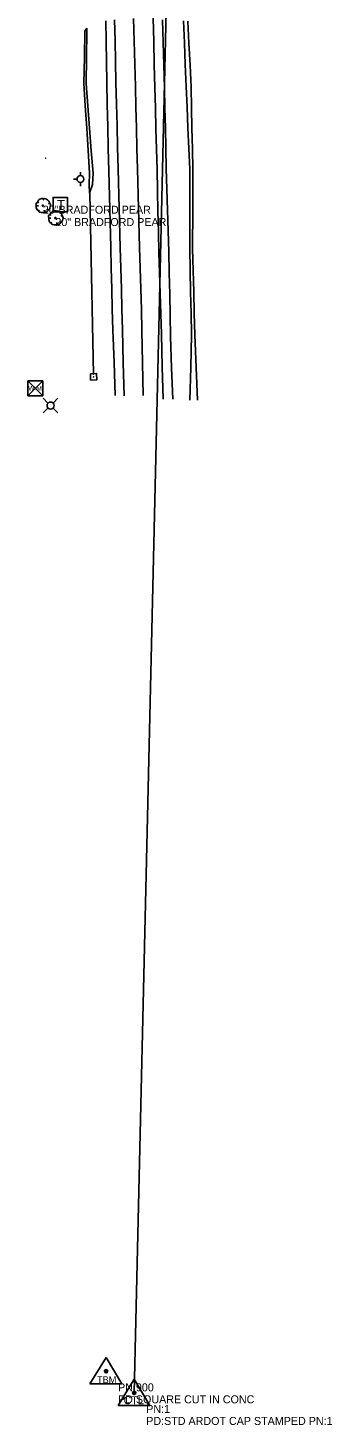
# Model space of a CAD drawing. Extents: x 1930288 to 1941089, y 588389 to 611475.
# Drawn here: x 1930835 to 1931025, y 596253 to 597126 of the extents above; entities that cross this region are included whole.
import ezdxf

# ---------------------------------------------------------------- set-up
doc = ezdxf.new("R2010")
doc.units = 0
for name, color, linetype in [('S_BASELINE', 7, 'Continuous'), ('S_DITCHLINE', 7, 'Continuous'), ('S_DRG_PT_SYM', 7, 'Continuous'), ('S_DROP_INLET', 7, 'Continuous'), ('S_EDGE_PAVEMENT', 7, 'Continuous'), ('S_MSC_PT_SYM', 7, 'Continuous'), ('S_PAVEMENT_CROWN', 7, 'Continuous'), ('S_PRIMARY_CTL', 7, 'Continuous'), ('S_PRIMARY_CTL_ANNOT', 7, 'Continuous'), ('S_SHOULDER', 7, 'Continuous'), ('S_STORM_SEWER', 7, 'Continuous'), ('S_TELEPHONE_UTILITIES', 7, 'Continuous'), ('S_TREE', 7, 'Continuous'), ('S_TREE_ANNOT', 7, 'Continuous'), ('S_UTILITY_POLE', 7, 'Continuous'), ('S_UTL_PT_SYM', 7, 'Continuous'), ('S_WATER_UTILITIES', 7, 'Continuous')]:
    doc.layers.add(name, color=color, linetype=linetype)

msp = doc.modelspace()

# ---------------------------------------------------------------- linework, layer by layer
at = {"layer": 'S_BASELINE'}
msp.add_line((1930901.19, 596273.28), (1930922.05, 597172.86), dxfattribs=at)
at = {"layer": 'S_DITCHLINE'}
for points in [[(1930935.96, 596893.42), (1930936.43, 596913.86), (1930936.9, 596934.29), (1930936.64, 596947.76), (1930936.39, 596961.23), (1930936.13, 596974.71), (1930935.87, 596988.18), (1930935.84, 597012.94), (1930935.8, 597037.7), (1930935.27, 597050.64), (1930934.74, 597063.57), (1930934.21, 597076.51), (1930933.67, 597089.44), (1930933.09, 597103.12), (1930932.51, 597116.8), (1930931.93, 597130.48)], [(1930940.76, 596893.51), (1930939.91, 596913.94), (1930939.07, 596934.38), (1930938.71, 596947.77), (1930938.36, 596961.16), (1930938.01, 596974.55), (1930937.65, 596987.94), (1930937.7, 597012.78), (1930937.75, 597037.63), (1930937.5, 597050.49), (1930937.24, 597063.34), (1930936.99, 597076.2), (1930936.73, 597089.05), (1930936.05, 597102.82), (1930935.37, 597116.58), (1930934.68, 597130.34)], [(1930871.61, 597125.83), (1930870.43, 597123.96), (1930870.11, 597107.71), (1930869.78, 597091.46), (1930870.65, 597077.43), (1930871.52, 597063.41), (1930872.39, 597049.39), (1930873.26, 597035.36), (1930873.14, 597028.29), (1930873.33, 597022.72)], [(1930871.61, 597125.83), (1930871.61, 597123.69), (1930871.36, 597107.55), (1930871.12, 597091.41), (1930872.21, 597077.38), (1930873.3, 597063.34), (1930874.39, 597049.31), (1930875.49, 597035.28), (1930875.21, 597028.14), (1930873.33, 597022.73)]]:
    msp.add_lwpolyline(points, dxfattribs=at)
at = {"layer": 'S_DRG_PT_SYM'}
msp.add_lwpolyline([(1930875.81, 596908.03), (1930875.81, 596908.08), (1930875.81, 596908.03), (1930875.76, 596908.03), (1930875.81, 596908.03), (1930875.81, 596907.98), (1930875.81, 596908.03), (1930875.86, 596908.03)], dxfattribs=at)
at = {"layer": 'S_DROP_INLET'}
msp.add_lwpolyline([(1930873.91, 596909.94), (1930877.76, 596910.21), (1930877.89, 596906.21), (1930873.97, 596906.02)], close=True, dxfattribs=at)
at = {"layer": 'S_EDGE_PAVEMENT'}
for points in [[(1930888.95, 597131.01), (1930889.24, 597118), (1930889.53, 597104.99), (1930889.82, 597091.97), (1930890.15, 597078.5), (1930890.49, 597065.03), (1930890.83, 597051.56), (1930891.16, 597038.09), (1930891.82, 597013.43), (1930892.48, 596988.78), (1930892.83, 596975.95), (1930893.19, 596963.12), (1930893.54, 596950.29), (1930893.89, 596937.46), (1930894.39, 596916.81), (1930894.9, 596896.15)], [(1930912.96, 597132.04), (1930913.35, 597117.63), (1930913.73, 597103.21), (1930914.11, 597088.8), (1930914.45, 597075.97), (1930914.78, 597063.15), (1930915.11, 597050.33), (1930915.44, 597037.5), (1930915.72, 597024.56), (1930916.01, 597011.62), (1930916.29, 596998.68), (1930916.58, 596985.74), (1930916.97, 596972.98), (1930917.37, 596960.21), (1930917.76, 596947.44), (1930918.15, 596934.67), (1930918.7, 596914.36), (1930919.25, 596894.06)]]:
    msp.add_lwpolyline(points, dxfattribs=at)
at = {"layer": 'S_MSC_PT_SYM'}
for points in [[(1930845.93, 597044.71), (1930845.93, 597044.76), (1930845.93, 597044.71), (1930845.88, 597044.71), (1930845.93, 597044.71), (1930845.93, 597044.66), (1930845.93, 597044.71), (1930845.98, 597044.71)], [(1930852.43, 597006.83), (1930852.43, 597006.88), (1930852.43, 597006.83), (1930852.38, 597006.83), (1930852.43, 597006.83), (1930852.43, 597006.78), (1930852.43, 597006.83), (1930852.48, 597006.83)]]:
    msp.add_lwpolyline(points, dxfattribs=at)
at = {"layer": 'S_PAVEMENT_CROWN'}
msp.add_lwpolyline([(1930900.73, 597131.95), (1930901.14, 597117.75), (1930901.56, 597103.54), (1930901.97, 597089.34), (1930902.27, 597076.48), (1930902.58, 597063.63), (1930902.88, 597050.77), (1930903.18, 597037.91), (1930903.84, 597013.39), (1930904.5, 596988.86), (1930904.88, 596975.92), (1930905.27, 596962.98), (1930905.65, 596950.04), (1930906.03, 596937.1), (1930906.41, 596916.76), (1930906.79, 596896.43)], dxfattribs=at)
at = {"layer": 'S_PRIMARY_CTL'}
for p, q in [((1930883.6, 596295.48), (1930873.57, 596278.96)), ((1930883.6, 596295.48), (1930893.42, 596278.96)), ((1930873.57, 596278.96), (1930893.42, 596278.96)), ((1930901.19, 596281.98), (1930891.16, 596265.47)), ((1930901.19, 596281.98), (1930911.01, 596265.47)), ((1930891.16, 596265.47), (1930911.01, 596265.47))]:
    msp.add_line(p, q, dxfattribs=at)
for centre, radius in [((1930883.6, 596286.78), 1.04), ((1930883.6, 596286.78), 0.609), ((1930883.6, 596286.78), 0.344), ((1930901.19, 596273.28), 1.04), ((1930901.19, 596273.28), 0.609), ((1930901.19, 596273.28), 0.344)]:
    msp.add_circle(centre, radius, dxfattribs=at)
at = {"layer": 'S_SHOULDER'}
for points in [[(1930883.43, 597130.36), (1930883.65, 597117.6), (1930883.87, 597104.84), (1930884.1, 597092.08), (1930884.4, 597078.25), (1930884.7, 597064.43), (1930885.01, 597050.61), (1930885.31, 597036.79), (1930885.95, 597012.83), (1930886.59, 596988.87), (1930886.91, 596975.99), (1930887.22, 596963.11), (1930887.53, 596950.23), (1930887.85, 596937.36), (1930888.6, 596916.91), (1930889.35, 596896.46)], [(1930918.82, 597130.98), (1930919.27, 597116.87), (1930919.71, 597102.76), (1930920.15, 597088.65), (1930920.4, 597076.06), (1930920.65, 597063.46), (1930920.9, 597050.86), (1930921.16, 597038.27), (1930921.57, 597025.24), (1930921.98, 597012.22), (1930922.39, 596999.2), (1930922.8, 596986.17), (1930923.06, 596972.95), (1930923.33, 596959.72), (1930923.59, 596946.5), (1930923.85, 596933.27), (1930924.52, 596913.69), (1930925.2, 596894.1)]]:
    msp.add_lwpolyline(points, dxfattribs=at)
at = {"layer": 'S_STORM_SEWER'}
msp.add_line((1930875.71, 596909.68), (1930873.41, 597022.7), dxfattribs=at)
at = {"layer": 'S_TELEPHONE_UTILITIES'}
msp.add_lwpolyline([(1930850.51, 597011.12), (1930850.51, 597020.12), (1930859.51, 597020.12), (1930859.51, 597011.12)], close=True, dxfattribs=at)
at = {"layer": 'S_TREE'}
for p, q in [((1930840.94, 597017.2), (1930841.44, 597016.62)), ((1930844.73, 597019.21), (1930844.35, 597018.36)), ((1930840.28, 597014.87), (1930841.4, 597014.87)), ((1930841.44, 597011.69), (1930841.9, 597012.39)), ((1930845.12, 597011.42), (1930845.04, 597012.2)), ((1930847.52, 597012.31), (1930847.06, 597012.74)), ((1930848.3, 597016.42), (1930847.64, 597016.15)), ((1930848.75, 597009.49), (1930849.26, 597008.91)), ((1930852.55, 597011.51), (1930852.16, 597010.65)), ((1930856.12, 597008.72), (1930855.46, 597008.45)), ((1930848.1, 597007.17), (1930849.22, 597007.17)), ((1930849.26, 597003.99), (1930849.72, 597004.69)), ((1930852.94, 597003.72), (1930852.86, 597004.49)), ((1930855.34, 597004.61), (1930854.88, 597005.04))]:
    msp.add_line(p, q, dxfattribs=at)
for centre in [(1930844.18, 597014.97), (1930851.99, 597007.26)]:
    msp.add_circle(centre, 0.341, dxfattribs=at)
for centre, major_axis, ratio, start_param, end_param in [((1930840.6, 597016.05), (0.31, 1.03), 0.646762, 0, 3.141593), ((1930842.84, 597018.17), (1.86, 1.08), 0.471018, 0, 3.141593), ((1930846.49, 597017.84), (-1.81, 1.36), 0.405113, 3.141593, 6.283186), ((1930840.91, 597013.4), (-0.61, 1.6), 0.420543, 6.283185, 9.424777), ((1930843.37, 597011.62), (-1.83, 0.19), 0.529943, 0, 3.141593), ((1930846.33, 597011.92), (1.09, 0.46), 0.711534, 3.141592, 6.283185), ((1930847.85, 597014.44), (0.46, 2.04), 0.482994, 3.141593, 6.283185), ((1930848.42, 597008.35), (0.31, 1.03), 0.646762, 0, 3.141593), ((1930850.66, 597010.46), (1.86, 1.08), 0.471018, 0, 3.141593), ((1930854.31, 597010.14), (-1.81, 1.36), 0.405113, 3.141593, 6.283186), ((1930855.67, 597006.73), (0.46, 2.04), 0.482994, 3.141593, 6.283185), ((1930848.73, 597005.7), (-0.61, 1.6), 0.420543, 6.283185, 9.424777), ((1930851.19, 597003.92), (-1.83, 0.19), 0.529943, 0, 3.141593), ((1930854.15, 597004.21), (1.09, 0.46), 0.711534, 3.141592, 6.283185)]:
    msp.add_ellipse(centre, major_axis=major_axis, ratio=ratio, start_param=start_param, end_param=end_param, dxfattribs=at)
at = {"layer": 'S_UTILITY_POLE'}
for p, q in [((1930867.63, 597033.74), (1930867.63, 597035.99)), ((1930865.54, 597031.61), (1930863.22, 597031.61)), ((1930867.71, 597027.19), (1930867.71, 597029.52)), ((1930847.38, 596891.68), (1930844.4, 596894.66)), ((1930850.56, 596891.68), (1930853.55, 596894.66)), ((1930847.38, 596888.5), (1930844.4, 596885.52)), ((1930850.56, 596888.5), (1930853.55, 596885.52))]:
    msp.add_line(p, q, dxfattribs=at)
for centre, radius in [((1930867.64, 597031.63), 2.13), ((1930848.98, 596890.1), 2.21)]:
    msp.add_circle(centre, radius, dxfattribs=at)
at = {"layer": 'S_UTL_PT_SYM'}
for points in [[(1930873.41, 597022.7), (1930873.41, 597022.75), (1930873.41, 597022.7), (1930873.36, 597022.7), (1930873.41, 597022.7), (1930873.41, 597022.65), (1930873.41, 597022.7), (1930873.46, 597022.7)], [(1930875.71, 596909.68), (1930875.71, 596909.73), (1930875.71, 596909.68), (1930875.66, 596909.68), (1930875.71, 596909.68), (1930875.71, 596909.63), (1930875.71, 596909.68), (1930875.76, 596909.68)], [(1930875.81, 596908.03), (1930875.81, 596908.08), (1930875.81, 596908.03), (1930875.76, 596908.03), (1930875.81, 596908.03), (1930875.81, 596907.98), (1930875.81, 596908.03), (1930875.86, 596908.03)]]:
    msp.add_lwpolyline(points, dxfattribs=at)
at = {"layer": 'S_WATER_UTILITIES'}
for p, q in [((1930834.89, 596905.65), (1930844.23, 596905.65)), ((1930834.89, 596905.65), (1930834.89, 596896.16)), ((1930834.89, 596905.65), (1930844.23, 596896.16)), ((1930844.23, 596905.65), (1930834.89, 596896.16)), ((1930844.23, 596905.65), (1930844.23, 596896.16)), ((1930834.89, 596896.16), (1930844.23, 596896.16))]:
    msp.add_line(p, q, dxfattribs=at)

# ---------------------------------------------------------------- texts
at = {"layer": 'S_PRIMARY_CTL'}
for s, height, p in [('TBM', 4.287, (1930877.95, 596279.39)), ('CTL', 5, (1930894.6, 596266.21))]:
    msp.add_text(s, height=height, rotation=360, dxfattribs=at).set_placement(p)
at = {"layer": 'S_PRIMARY_CTL_ANNOT'}
for s, p in [('PN:900', (1930891.1, 596274.28)), ('PD:SQUARE CUT IN CONC', (1930891.1, 596266.78)), ('PN:1', (1930908.69, 596260.78)), ('PD:STD ARDOT CAP STAMPED PN:1', (1930908.69, 596253.28))]:
    msp.add_text(s, height=5, dxfattribs=at).set_placement(p)
at = {"layer": 'S_TELEPHONE_UTILITIES'}
msp.add_text('T', height=6, rotation=360, dxfattribs=at).set_placement((1930853.07, 597012.62))
at = {"layer": 'S_TREE_ANNOT'}
for s, p in [('20"BRADFORD PEAR', (1930844.18, 597009.97)), ('20" BRADFORD PEAR', (1930851.99, 597002.26))]:
    msp.add_text(s, height=5, dxfattribs=at).set_placement(p)
at = {"layer": 'S_WATER_UTILITIES'}
msp.add_text('W M', height=3, rotation=360, dxfattribs=at).set_placement((1930835.09, 596899.42))

doc.saveas('drawing.dxf')
